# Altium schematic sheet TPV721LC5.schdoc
size 127 x 101 mm
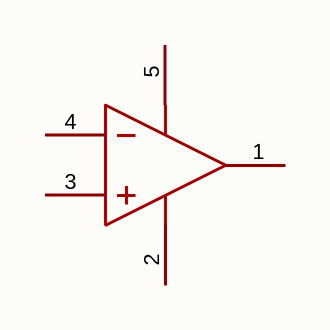
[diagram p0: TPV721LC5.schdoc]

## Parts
U?  tpv721lc5  [SOT-353_L2.1-W1.3-P0.65-LS2.3-BR]  (value not drawn)

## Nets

Not connected (* = marked no-connect by the designer): U? 1(OUT) 2(V-) 3(IN+) 4(IN-) 5(V+)

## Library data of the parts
U? = tpv721lc5: 放大器数:1;轨到轨:轨到轨输入,轨到轨输出;增益带宽积(GBW):8MHz;输入失调电压(Vos):2.5mV;压摆率(SR):6V/us;输入偏置电流(Ib):10pA;; Manufacturer: TECH PUBLIC(台舟); AddInBom: yes; ModelId: 4e853f80e521480faffa12d625b9ef27; ModelName: SOT-353-5P_L2.0-W1.3-H1.1-LS2.0-P0.65; ModelTransform: 83.17133,78.74,0,180,0,0,-0.0005,0,0; Number of Channels: 1; Maximum Power Supply Range (Vdd-Vss): 5.5V; Gain Bandwidth Product: 8MHz; Vos - Input Offset Voltage: 2.5mV; Input Offset Voltage Drift(Vos TC): 600nV/℃; Slew Rate: 6V/us; Ib - Input Bias Current: 10pA; Input Offset Current(Ios): 5pA; Input Voltage Noise Density: 8nV/√Hz@1kHz; Common Mode Rejection Ratio(CMRR): 95dB; Quiescent Current: 510uA; Output Current: 26mA; Single supply: 2.2V~5.5V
